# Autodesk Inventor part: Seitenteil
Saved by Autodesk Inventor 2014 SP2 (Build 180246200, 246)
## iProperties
Created: 2015-07
Part Number: Seitenteil
Material: Generisch
Document SubType Name: Modeling
Designer: e_krauts
Density: 1 g/cm^3
Appearance: Vorgabe
Author: e_krauts
Sending System: SolidWorks 2011
Last Author: e_boekem
Sachnummer: NWS 100-00-01
Erstellt durch: XYZ
Werkstoff: AlCu4PbMg
Einheit: Stck.
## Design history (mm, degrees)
node "Seitenteil.ipt1"
node "M5 Gewindebohrung1"
node "Basis1"
